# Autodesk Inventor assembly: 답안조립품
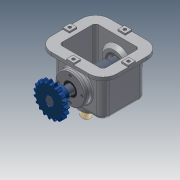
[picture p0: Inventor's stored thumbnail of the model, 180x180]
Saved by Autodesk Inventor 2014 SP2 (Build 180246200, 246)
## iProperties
Created: 2014-11
Part Number: 답안조립품
Document SubType Name: Assembly
Designer: 201-12
Author: 201-12
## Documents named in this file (13)
- C:\Users\201-12\Desktop\441122V1019\답안조립품.iam
- C:\Users\201-12\Desktop\441122V1019\본체.ipt
- C:\Users\201-12\Desktop\441122V1019\5-체인 스프로킷.ipt
- C:\Users\201-12\Desktop\441122V1019\M4x0.5.ipt
- C:\Users\201-12\Desktop\441122V1019\뒤커버.ipt
- C:\Users\201-12\Desktop\441122V1019\멈춤나사 M5x0.5.ipt
- C:\Users\201-12\Desktop\441122V1019\베어링 6205.ipt
- C:\Users\201-12\Desktop\441122V1019\부시.ipt
- C:\Users\201-12\Desktop\441122V1019\슬라이드.ipt
- C:\Users\201-12\Desktop\441122V1019\앞커버.ipt
- C:\Users\201-12\Desktop\441122V1019\오일실.ipt
- C:\Users\201-12\Desktop\441122V1019\키 8x8.ipt
- C:\Users\201-12\Desktop\441122V1019\편심축.ipt
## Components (9 placed, 2 different names)
1. 5-체인 스프로킷:1
2. M4x0.5:1
3. M4x0.5:3
4. M4x0.5:4
5. M4x0.5:5
6. M4x0.5:2
7. M4x0.5:6
8. M4x0.5:7
9. M4x0.5:8
